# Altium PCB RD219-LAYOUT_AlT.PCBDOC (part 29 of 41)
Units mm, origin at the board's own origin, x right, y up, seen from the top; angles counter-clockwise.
Board outline 209.75 x 159.97 mm, 2 copper layers (TOP, BOTTOM), stack 0 mm thick; 398 components, 199 nets, 1469 pads, 0 vias.
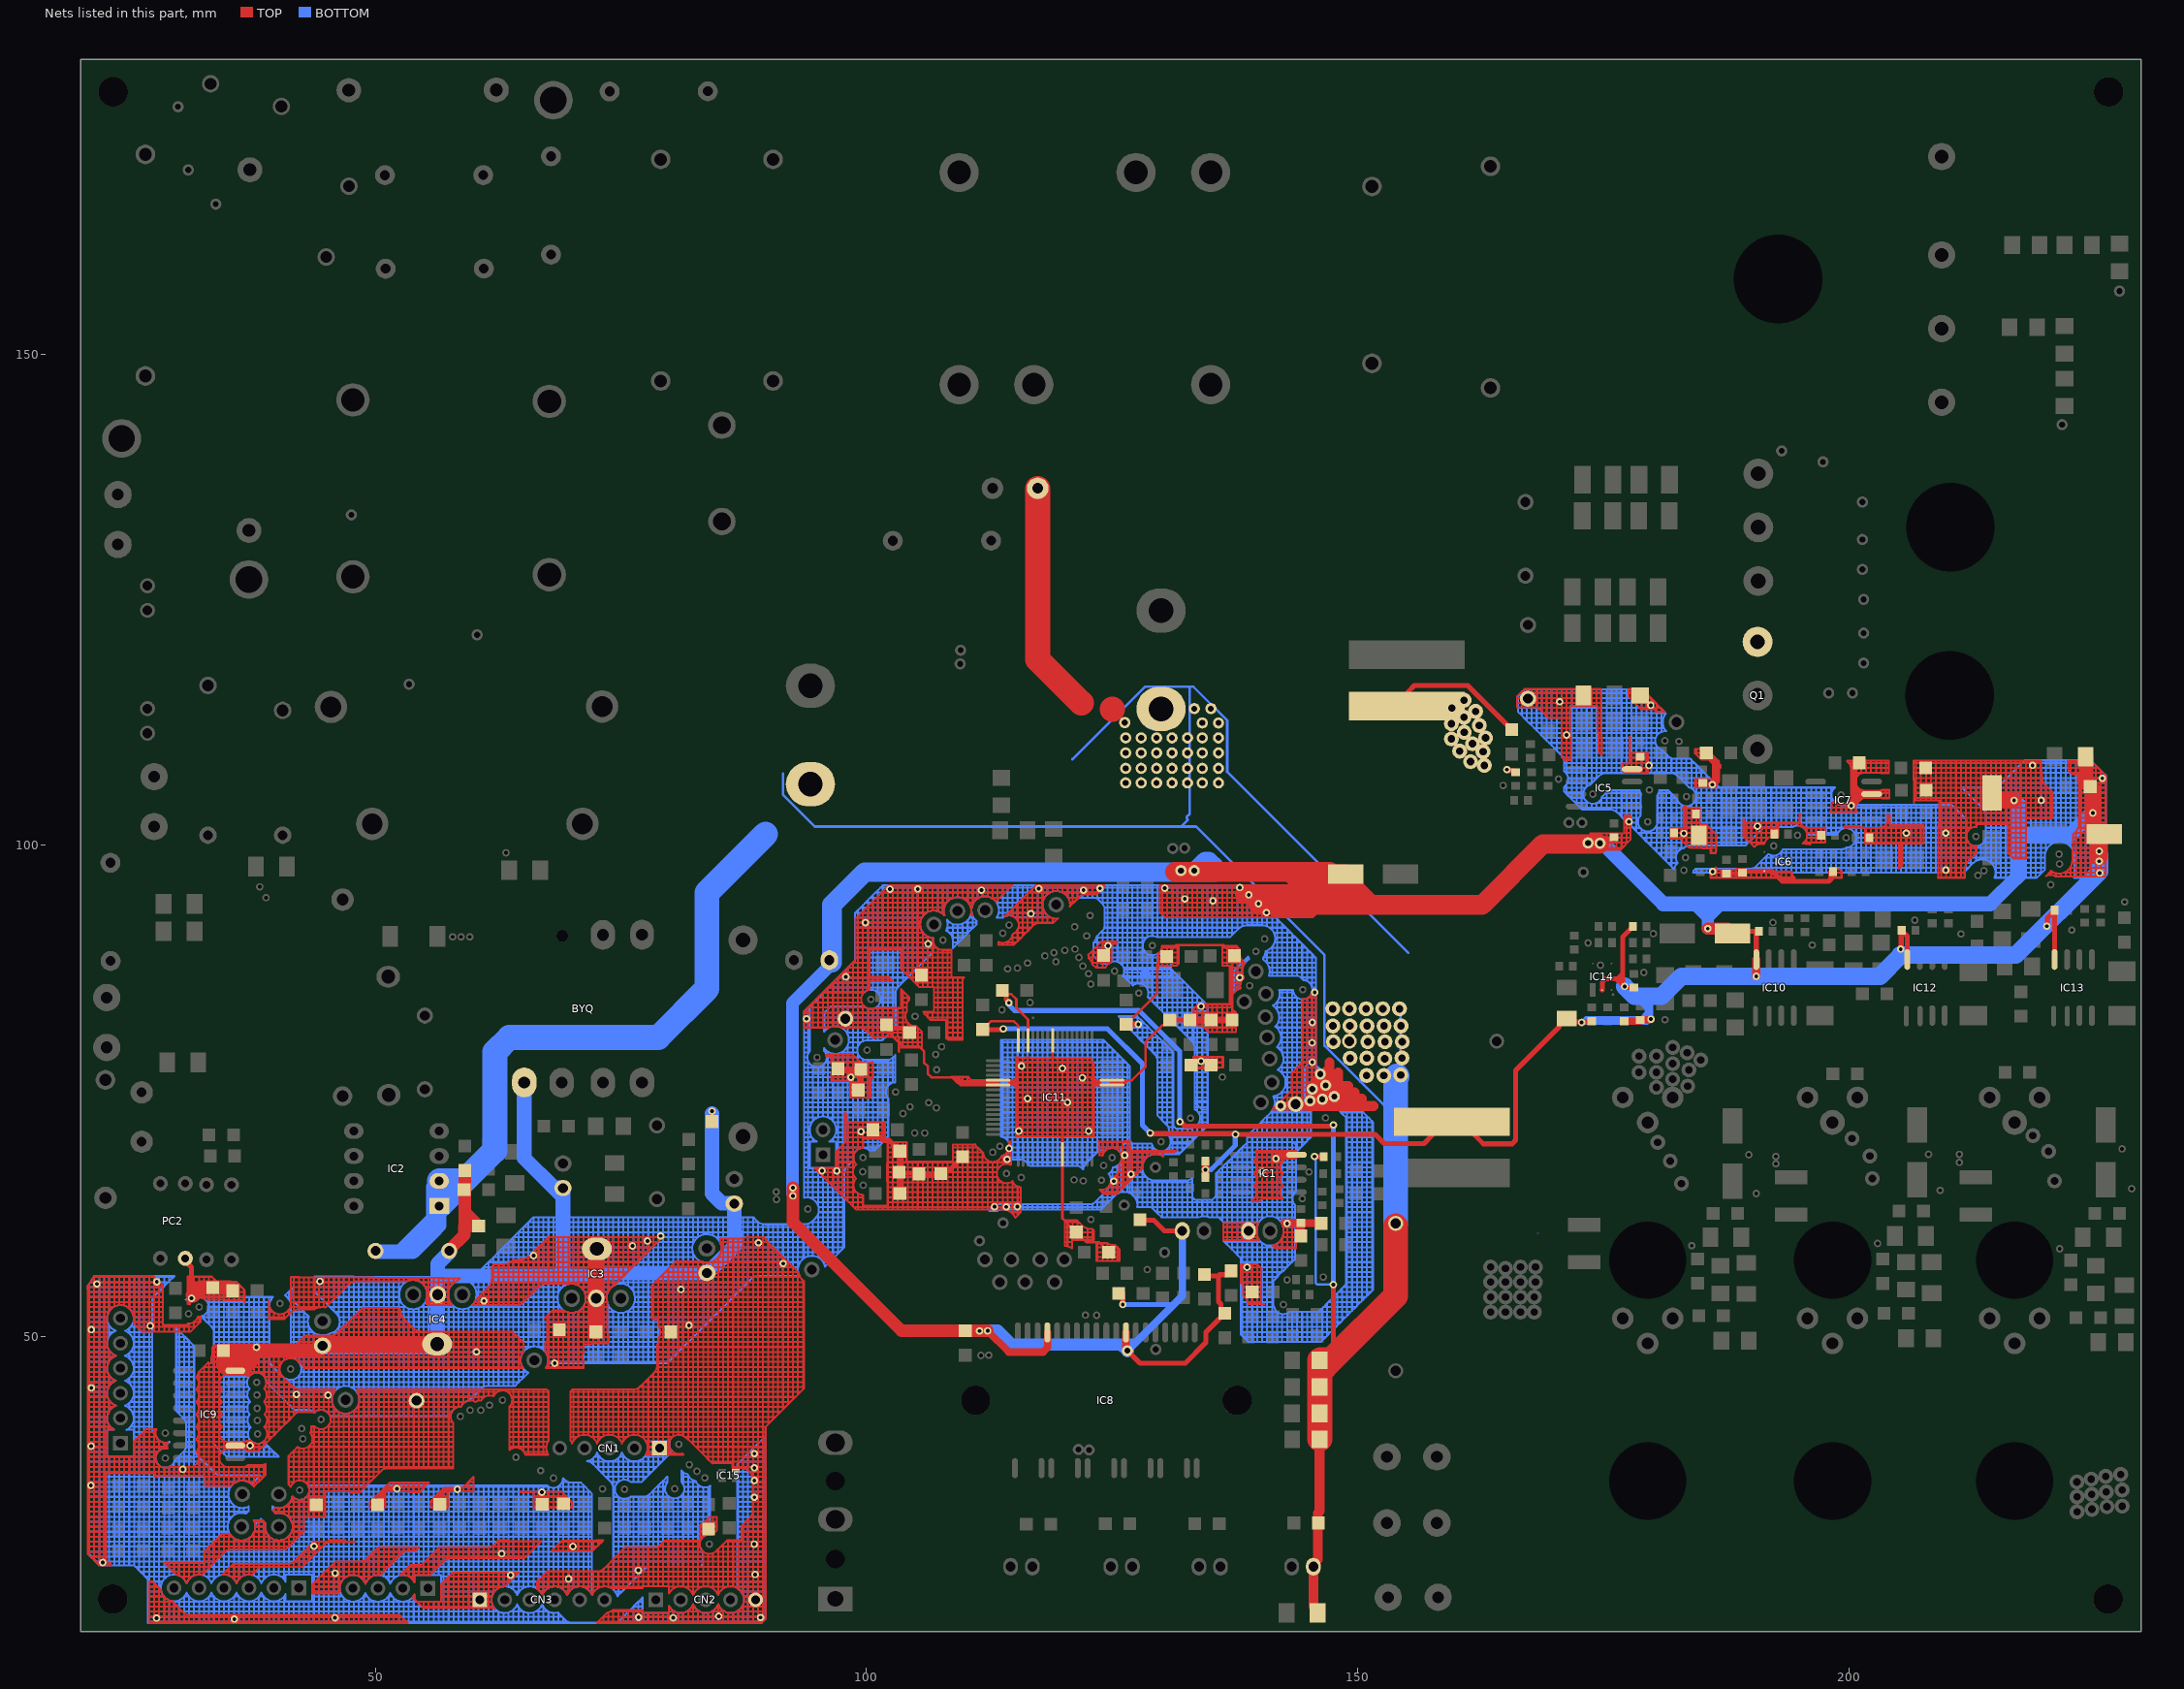
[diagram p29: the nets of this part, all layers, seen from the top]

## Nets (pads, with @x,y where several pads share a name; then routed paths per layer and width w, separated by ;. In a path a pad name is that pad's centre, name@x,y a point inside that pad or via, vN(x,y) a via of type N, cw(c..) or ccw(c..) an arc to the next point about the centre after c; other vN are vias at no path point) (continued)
GND: (continued)
  BOTTOM w0.203: 88.453,36.256 88.961,36.256 ; pad.@88.453,36.764 88.453,37.272 ; pad.@88.453,36.764 pad.@88.961,36.764 ; 88.453,37.272 pad.@88.453,37.78 ; 88.453,37.272 88.961,37.272 ; pad.@88.453,37.78 pad.@88.453,38.288 ; pad.@88.453,37.78 88.961,37.78 ; pad.@88.453,38.288 88.453,38.634 ; pad.@88.453,38.288 88.961,38.288 ; 88.453,38.634 88.615,38.796 ; 88.453,56.027 cw(c88.875,55.433) 88.518,56.068 ; 88.453,56.027 cw(c88.875,55.433) 88.518,56.068 ; 88.453,56.027 88.453,56.068 ; 88.453,56.068 88.453,56.576 ; 88.453,56.068 88.518,56.068 ; 88.453,56.576 88.453,57.084 ; 88.453,56.576 88.961,56.576 ; 88.453,57.084 88.453,57.592 ; 88.453,57.084 88.961,57.084 ; 88.453,57.592 88.453,58.1 ; 88.453,57.592 88.961,57.592 ; 88.453,58.1 88.453,58.608 ; 88.453,58.1 88.961,58.1 ; 88.453,58.608 88.453,59.116 ; 88.453,58.608 88.961,58.608 ; 88.453,59.116 88.961,59.116 ; 88.453,59.116 88.453,59.624 ; 88.453,59.624 88.453,60.132 ; 88.453,59.624 pad.@88.961,59.624 ; 88.453,60.132 88.453,60.64 ; 88.453,60.132 88.961,60.132 ; 88.453,60.64 88.961,60.64 ; 88.453,60.64 88.453,61.148 ; 88.453,61.148 88.453,61.656 ; 88.453,61.148 88.961,61.148 ; 88.453,61.656 88.961,61.656 ; 88.453,61.656 88.453,62.164 ; 88.453,62.164 88.464,62.164 88.831,61.798 ; 88.518,56.068 cw(c88.875,55.433) 88.875,56.162 ; 88.518,56.068 cw(c88.875,55.433) 88.875,56.162 ; 88.615,38.796 88.961,38.796 ; 88.615,38.796 88.961,39.142 ; 88.831,61.798 ccw(c89.705,62.672) 88.961,61.684 ; 88.831,61.798 ccw(c89.705,62.672) 88.961,61.684 ; 88.875,56.162 88.961,56.162 ; 88.961,20.889 88.961,21.016 ; 88.961,20.889 89.215,20.889 89.342,21.016 ; 88.961,21.016 pad.@88.961,21.524 ; 88.961,21.016 89.342,21.016 ; pad.@88.961,21.524 88.961,22.032 ; pad.@88.961,21.524 pad.@89.469,21.524 ; 88.961,22.032 CN2.5@88.961,22.54 ; 88.961,22.032 89.469,22.032 ; CN2.5@88.961,22.54 CN2.5@88.961,23.048 ; CN2.5@88.961,22.54 89.469,22.54 ; CN2.5@88.961,23.048 89.469,23.048 ; CN2.5@88.961,23.048 CN2.5@88.961,23.556 ; CN2.5@88.961,23.556 88.961,24.064 ; CN2.5@88.961,23.556 89.469,23.556 ; 88.961,24.064 88.961,24.572 ; 88.961,24.064 89.469,24.064 ; 88.961,24.572 89.469,24.572 ; 88.961,24.572 88.961,25.08 ; 88.961,25.08 pad.@88.961,25.588 ; 88.961,25.08 89.469,25.08 ; pad.@88.961,25.588 89.469,25.588 ; pad.@88.961,25.588 88.961,26.096 ; 88.961,26.096 88.961,26.604 ; 88.961,26.096 89.469,26.096 ; 88.961,26.604 88.961,27.112 ; 88.961,26.604 89.469,26.604 ; 88.961,27.112 88.961,27.62 ; 88.961,27.112 89.469,27.112 ; 88.961,27.62 88.961,28.128 ; 88.961,27.62 89.469,27.62 ; 88.961,28.128 88.961,28.636 ; 88.961,28.128 89.469,28.128 ; 88.961,28.636 89.469,28.636 ; 88.961,28.636 88.961,29.144 ; 88.961,29.144 88.961,29.652 ; 88.961,29.144 89.469,29.144 ; 88.961,29.652 88.961,30.16 ; 88.961,29.652 89.469,29.652 ; 88.961,30.16 88.961,30.668 ; 88.961,30.16 89.469,30.16 ; 88.961,30.668 88.961,31.176 ; 88.961,30.668 89.469,30.668 ; 88.961,31.176 88.961,31.684 ; 88.961,31.176 89.469,31.176 ; 88.961,31.684 88.961,32.192 ; 88.961,31.684 89.469,31.684 ; 88.961,32.192 88.961,32.7 ; 88.961,32.192 89.469,32.192 ; 88.961,32.7 88.961,33.208 ; 88.961,32.7 89.469,32.7 ; 88.961,33.208 89.469,33.208 ; 88.961,33.208 pad.@88.961,33.716 ; pad.@88.961,33.716 88.961,34.224 ; pad.@88.961,33.716 89.469,33.716 ; 88.961,34.224 88.961,34.732 ; 88.961,34.224 89.469,34.224 ; 88.961,34.732 88.961,35.24 ; 88.961,34.732 89.469,34.732 ; 88.961,35.24 89.469,35.24 ; 88.961,35.24 88.961,35.748 ; 88.961,35.748 88.961,36.256 ; 88.961,35.748 89.469,35.748 ; 88.961,36.256 89.469,36.256 ; 88.961,36.256 pad.@88.961,36.764 ; pad.@88.961,36.764 88.961,37.272 ; pad.@88.961,36.764 89.469,36.764 ; 88.961,37.272 88.961,37.78 ; 88.961,37.272 89.469,37.272 ; 88.961,37.78 89.469,37.78 ; 88.961,37.78 88.961,38.288 ; 88.961,38.288 88.961,38.796 ; 88.961,38.288 89.469,38.288 ; 88.961,38.796 88.961,39.142 ; 88.961,38.796 89.469,38.796 ; 88.961,39.142 89.123,39.304 ; 88.961,56.162 88.961,56.576 ; 88.961,56.162 89.469,56.162 ; 88.961,56.576 88.961,57.084 ; 88.961,56.576 89.469,56.576 ; 88.961,57.084 88.961,57.592 ; 88.961,57.084 89.469,57.084 ; 88.961,57.592 88.961,58.1 ; 88.961,57.592 89.469,57.592 ; 88.961,58.1 88.961,58.608 ; 88.961,58.1 89.469,58.1 ; 88.961,58.608 88.961,59.116 ; 88.961,58.608 89.469,58.608 ; 88.961,59.116 pad.@88.961,59.624 ; 88.961,59.116 89.469,59.116 ; pad.@88.961,59.624 88.961,60.132 ; pad.@88.961,59.624 89.469,59.624 ; 88.961,60.132 88.961,60.64 ; 88.961,60.132 89.469,60.132 ; 88.961,60.64 89.469,60.64 ; 88.961,60.64 88.961,61.148 ; 88.961,61.148 88.961,61.656 ; 88.961,61.148 89.469,61.148 ; 88.961,61.656 88.961,61.684 ; 88.961,61.656 89,61.656 ; 88.961,61.684 ccw(c89.705,62.672) 89,61.656 ; 88.961,61.684 ccw(c89.705,62.672) 89,61.656 ; 89,61.656 ccw(c89.705,62.672) 89.469,61.458 ; 89,61.656 ccw(c89.705,62.672) 89.469,61.458 ; 89.123,39.304 89.469,39.65 ; 89.123,39.304 89.469,39.304 ; 89.342,21.016 89.469,21.143 ; 89.469,21.143 pad.@89.469,21.524 ; 89.469,21.143 89.723,21.397 89.723,21.524 ; pad.@89.469,21.524 89.723,21.524 ; pad.@89.469,21.524 89.469,22.032 ; 89.469,22.032 89.469,22.54 ; 89.469,22.032 89.723,22.032 ; 89.469,22.54 89.469,23.048 ; 89.469,22.54 89.723,22.54 ; 89.469,23.048 89.723,23.048 ; 89.469,23.048 89.469,23.556 ; 89.469,23.556 89.469,24.064 ; 89.469,23.556 89.723,23.556 ; 89.469,24.064 89.469,24.572 ; 89.469,24.064 89.723,24.064 ; 89.469,24.572 89.469,25.08 ; 89.469,24.572 89.723,24.572 ; 89.469,25.08 89.469,25.588 ; 89.469,25.08 89.723,25.08 ; 89.469,25.588 89.469,26.096 ; 89.469,25.588 89.723,25.588 ; 89.469,26.096 89.469,26.604 ; 89.469,26.096 89.723,26.096 ; 89.469,26.604 89.469,27.112 ; 89.469,26.604 89.723,26.604 ; 89.469,27.112 89.469,27.62 ; 89.469,27.112 89.723,27.112 ; 89.469,27.62 89.469,28.128 ; 89.469,27.62 89.723,27.62 ; 89.469,28.128 89.469,28.636 ; 89.469,28.128 89.723,28.128 ; 89.469,28.636 89.469,29.144 ; 89.469,28.636 89.723,28.636 ; 89.469,29.144 89.469,29.652 ; 89.469,29.144 89.723,29.144 ; 89.469,29.652 89.469,30.16 ; 89.469,29.652 89.723,29.652 ; 89.469,30.16 89.469,30.668 ; 89.469,30.16 89.723,30.16 ; 89.469,30.668 89.469,31.176 ; 89.469,30.668 89.723,30.668 ; 89.469,31.176 89.469,31.684 ; 89.469,31.176 89.723,31.176 ; 89.469,31.684 89.469,32.192 ; 89.469,31.684 89.723,31.684 ; 89.469,32.192 89.469,32.7 ; 89.469,32.192 89.723,32.192 ; 89.469,32.7 89.469,33.208 ; 89.469,32.7 89.723,32.7 ; 89.469,33.208 89.469,33.716 ; 89.469,33.208 89.723,33.208 ; 89.469,33.716 89.469,34.224 ; 89.469,33.716 89.723,33.716 ; 89.469,34.224 89.469,34.732 ; 89.469,34.224 89.723,34.224 ; 89.469,34.732 89.469,35.24 ; 89.469,34.732 89.723,34.732 ; 89.469,35.24 89.469,35.748 ; 89.469,35.24 89.723,35.24 ; 89.469,35.748 89.469,36.256 ; 89.469,35.748 89.723,35.748 ; 89.469,36.256 89.469,36.764 ; 89.469,36.256 89.723,36.256 ; 89.469,36.764 89.469,37.272 ; 89.469,36.764 89.723,36.764 ; 89.469,37.272 89.469,37.78 ; 89.469,37.272 89.723,37.272 ; 89.469,37.78 89.469,38.288 ; 89.469,37.78 89.723,37.78 ; 89.469,38.288 89.469,38.796 ; 89.469,38.288 89.723,38.288 ; 89.469,38.796 89.469,39.304 ; 89.469,38.796 89.723,38.796 ; 89.469,39.304 89.469,39.65 ; 89.469,39.304 89.723,39.304 ; 89.469,39.65 89.631,39.812 ; 89.469,56.162 89.469,56.576 ; 89.469,56.162 89.977,56.162 ; 89.469,56.576 89.469,57.084 ; 89.469,56.576 89.977,56.576 ; 89.469,57.084 89.469,57.592 ; 89.469,57.084 89.977,57.084 ; 89.469,57.592 89.469,58.1 ; 89.469,57.592 89.977,57.592 ; 89.469,58.1 89.469,58.608 ; 89.469,58.1 89.977,58.1 ; 89.469,58.608 89.469,59.116 ; 89.469,58.608 89.977,58.608 ; 89.469,59.116 89.977,59.116 ; 89.469,59.116 89.469,59.624 ; 89.469,59.624 89.469,60.132 ; 89.469,59.624 89.977,59.624 ; 89.469,60.132 89.469,60.64 ; 89.469,60.132 89.977,60.132 ; 89.469,60.64 89.469,61.148 ; 89.469,60.64 89.977,60.64 ; 89.469,61.148 89.977,61.148 ; 89.469,61.148 89.469,61.458 ; 89.469,61.458 ccw(c89.705,62.672) 89.705,61.435 ; 89.469,61.458 ccw(c89.705,62.672) 89.705,61.435 ; 89.631,39.812 89.723,39.812 ; 89.631,39.812 89.723,39.904 89.723,39.812 ; 89.705,61.435 89.977,61.435 ; 89.723,21.524 89.723,22.032 ; 89.723,22.032 89.723,22.54 ; 89.723,22.54 89.723,23.048 ; 89.723,23.048 89.723,23.556 ; 89.723,23.556 89.723,24.064 ; 89.723,24.064 89.723,24.572 ; 89.723,24.572 89.723,25.08 ; 89.723,25.08 89.723,25.588 ; 89.723,25.588 89.723,26.096 ; 89.723,26.096 89.723,26.604 ; 89.723,26.604 89.723,27.112 ; 89.723,27.112 89.723,27.62 ; 89.723,27.62 89.723,28.128 ; 89.723,28.128 89.723,28.636 ; 89.723,28.636 89.723,29.144 ; 89.723,29.144 89.723,29.652 ; 89.723,29.652 89.723,30.16 ; 89.723,30.16 89.723,30.668 ; 89.723,30.668 89.723,31.176 ; 89.723,31.176 89.723,31.684 ; 89.723,31.684 89.723,32.192 ; 89.723,32.192 89.723,32.7 ; 89.723,32.7 89.723,33.208 ; 89.723,33.208 89.723,33.716 ; 89.723,33.716 89.723,34.224 ; 89.723,34.224 89.723,34.732 ; 89.723,34.732 89.723,35.24 ; 89.723,35.24 89.723,35.748 ; 89.723,35.748 89.723,36.256 ; 89.723,36.256 89.723,36.764 ; 89.723,36.764 89.723,37.272 ; 89.723,37.272 89.723,37.78 ; 89.723,37.78 89.723,38.288 ; 89.723,38.288 89.723,38.796 ; 89.723,38.796 89.723,39.304 ; 89.723,39.304 89.723,39.812 ; 89.977,56.162 89.977,56.576 ; 89.977,56.162 90.485,56.162 ; 89.977,56.576 89.977,57.084 ; 89.977,56.576 90.485,56.576 ; 89.977,57.084 89.977,57.592 ; 89.977,57.084 90.485,57.084 ; 89.977,57.592 89.977,58.1 ; 89.977,57.592 90.485,57.592 ; 89.977,58.1 89.977,58.608 ; 89.977,58.1 90.485,58.1 ; 89.977,58.608 89.977,59.116 ; 89.977,58.608 90.485,58.608 ; 89.977,59.116 89.977,59.624 ; 89.977,59.116 90.485,59.116 ; 89.977,59.624 89.977,60.132 ; 89.977,59.624 90.485,59.624 ; 89.977,60.132 89.977,60.64 ; 89.977,60.132 90.485,60.132 ; 89.977,60.64 89.977,61.148 ; 89.977,60.64 90.485,60.64 ; 89.977,61.148 89.977,61.435 ; 89.977,61.148 90.485,61.148 ; 89.977,61.435 90.485,61.435 ; 90.485,56.162 90.485,56.576 ; 90.485,56.162 90.993,56.162 ; 90.485,56.576 90.485,57.084 ; 90.485,56.576 90.993,56.576 ; 90.485,57.084 90.485,57.592 ; 90.485,57.084 90.993,57.084 ; 90.485,57.592 90.485,58.1 ; 90.485,57.592 90.993,57.592 ; 90.485,58.1 90.485,58.608 ; 90.485,58.1 90.993,58.1 ; 90.485,58.608 90.485,59.116 ; 90.485,58.608 90.993,58.608 ; 90.485,59.116 90.485,59.624 ; 90.485,59.116 90.993,59.116 ; 90.485,59.624 90.485,60.132 ; 90.485,59.624 90.993,59.624 ; 90.485,60.132 90.485,60.64 ; 90.485,60.132 90.993,60.132 ; 90.485,60.64 90.485,61.148 ; 90.485,60.64 90.993,60.64 ; 90.485,61.148 90.485,61.435 ; 90.485,61.148 90.993,61.148 ; 90.485,61.435 90.993,61.435 ; 90.993,56.162 90.993,56.576 ; 90.993,56.162 91.501,56.162 ; 90.993,56.576 90.993,57.084 ; 90.993,56.576 91.501,56.576 ; 90.993,57.084 90.993,57.592 ; 90.993,57.084 pad.@91.501,57.084 ; 90.993,57.592 90.993,58.1 ; 90.993,57.592 pad.@91.501,57.592 ; 90.993,58.1 90.993,58.608 ; 90.993,58.1 91.501,58.1 ; 90.993,58.608 90.993,59.116 ; 90.993,58.608 91.501,58.608 ; 90.993,59.116 90.993,59.624 ; 90.993,59.116 91.501,59.116 ; 90.993,59.624 90.993,60.132 ; 90.993,59.624 91.501,59.624 ; 90.993,60.132 90.993,60.64 ; 90.993,60.132 91.501,60.132 ; 90.993,60.64 90.993,61.148 ; 90.993,60.64 91.501,60.64 ; 90.993,61.148 90.993,61.435 ; 90.993,61.148 91.501,61.148 ; 90.993,61.435 91.501,61.435 ; 91.501,56.162 91.501,56.576 ; 91.501,56.162 92.009,56.162 ; 91.501,56.576 pad.@91.501,57.084 ; 91.501,56.576 92.009,56.576 ; pad.@91.501,57.084 pad.@91.501,57.592 ; pad.@91.501,57.084 92.009,57.084 ; pad.@91.501,57.592 91.501,58.1 ; pad.@91.501,57.592 92.009,57.592 ; 91.501,58.1 91.501,58.608 ; 91.501,58.1 92.009,58.1 ; 91.501,58.608 91.501,59.116 ; 91.501,58.608 92.009,58.608 ; 91.501,59.116 91.501,59.624 ; 91.501,59.116 92.009,59.116 ; 91.501,59.624 91.501,60.132 ; 91.501,59.624 92.009,59.624 ; 91.501,60.132 91.501,60.64 ; 91.501,60.132 92.009,60.132 ; 91.501,60.64 91.501,61.148 ; 91.501,60.64 92.009,60.64 ; 91.501,61.148 91.501,61.435 ; 91.501,61.148 92.009,61.148 ; 91.501,61.435 92.009,61.435 ; 92.009,56.162 92.009,56.576 ; 92.009,56.162 92.517,56.162 ; 92.009,56.576 92.009,57.084 ; 92.009,56.576 92.517,56.576 ; 92.009,57.084 92.009,57.592 ; 92.009,57.084 92.517,57.084 ; 92.009,57.592 92.009,58.1 ; 92.009,57.592 92.517,57.592 ; 92.009,58.1 92.009,58.608 ; 92.009,58.1 92.517,58.1 ; 92.009,58.608 92.009,59.116 ; 92.009,58.608 92.517,58.608 ; 92.009,59.116 92.009,59.624 ; 92.009,59.116 92.517,59.116 ; 92.009,59.624 92.009,60.132 ; 92.009,59.624 92.517,59.624 ; 92.009,60.132 92.009,60.64 ; 92.009,60.132 92.517,60.132 ; 92.009,60.64 92.009,61.148 ; 92.009,60.64 92.517,60.64 ; 92.009,61.148 92.009,61.435 ; 92.009,61.148 92.517,61.148 ; 92.009,61.435 92.517,61.435 ; 92.517,56.162 93.025,56.162 ; 92.517,56.162 92.517,56.576 ; 92.517,56.576 93.025,56.576 ; 92.517,56.576 92.517,57.084 ; 92.517,57.084 93.025,57.084 ; 92.517,57.084 92.517,57.592 ; 92.517,57.592 92.517,58.1 ; 92.517,57.592 93.025,57.592 ; 92.517,58.1 93.025,58.1 ; 92.517,58.1 92.517,58.608 ; 92.517,58.608 92.517,59.116 ; 92.517,58.608 93.025,58.608 ; 92.517,59.116 93.025,59.116 ; 92.517,59.116 92.517,59.624 ; 92.517,59.624 92.517,60.132 ; 92.517,59.624 93.025,59.624 ; 92.517,60.132 92.517,60.64 ; 92.517,60.132 93.025,60.132 ; 92.517,60.64 93.025,60.64 ; 92.517,60.64 92.517,61.148 ; 92.517,61.148 92.517,61.435 ; 92.517,61.148 93.025,61.148 ; 92.517,61.435 93.025,61.435 ; 93.025,56.162 93.025,56.576 ; 93.025,56.576 93.025,56.717 ; 93.025,56.576 93.044,56.576 ; 93.025,56.717 cw(c94.422,56.83) 93.025,56.943 ; 93.025,56.717 ccw(c94.422,56.83) 93.044,56.576 ; 93.025,56.943 cw(c94.422,56.83) 93.044,57.084 ; 93.025,56.943 93.025,57.084 ; 93.025,57.084 93.025,57.592 ; 93.025,57.084 93.044,57.084 ; 93.025,57.592 93.025,58.1 ; 93.025,57.592 93.246,57.592 ; 93.025,58.1 93.025,58.608 ; 93.025,58.1 93.533,58.1 ; 93.025,58.608 93.025,59.116 ; 93.025,58.608 93.533,58.608 ; 93.025,59.116 93.025,59.624 ; 93.025,59.116 93.533,59.116 ; 93.025,59.624 93.025,60.132 ; 93.025,59.624 93.533,59.624 ; 93.025,60.132 93.025,60.64 ; 93.025,60.132 93.533,60.132 ; 93.025,60.64 93.025,61.148 ; 93.025,60.64 93.533,60.64 ; 93.025,61.148 93.025,61.435 ; 93.025,61.148 93.533,61.148 ; 93.025,61.435 93.533,61.435 ; 93.044,57.084 cw(c94.422,56.83) 93.246,57.592 ; 93.246,57.592 cw(c94.422,56.83) 93.247,57.593 cw(c94.422,56.83) 93.533,57.914 ; 93.533,57.914 cw(c94.422,56.83) 93.659,58.005 cw(c94.422,56.83) 93.66,58.006 ; 93.533,57.914 93.533,58.1 ; 93.533,58.1 93.533,58.608 ; 93.533,58.1 93.66,58.1 ; 93.533,58.608 93.533,59.116 ; 93.533,58.608 93.66,58.608 ; 93.533,59.116 93.533,59.624 ; 93.533,59.116 93.66,59.116 ; 93.533,59.624 93.533,60.132 ; 93.533,59.624 93.66,59.624 ; 93.533,60.132 93.533,60.64 ; 93.533,60.132 93.66,60.132 ; 93.533,60.64 93.533,61.148 ; 93.533,60.64 93.66,60.64 ; 93.533,61.148 93.533,61.435 ; 93.533,61.148 93.66,61.148 ; 93.533,61.435 93.66,61.435 ; 93.66,58.006 cw(c94.422,56.83) 93.829,58.1 ; 93.66,58.006 93.66,58.1 ; 93.66,58.1 93.66,58.608 ; 93.66,58.1 93.829,58.1 ; 93.66,58.608 93.66,59.116 ; 93.66,58.608 94.041,58.608 ; 93.66,59.116 93.66,59.624 ; 93.66,59.116 94.041,59.116 ; 93.66,59.624 94.041,59.624 ; 93.66,59.624 93.66,60.132 ; 93.66,60.132 93.66,60.64 ; 93.66,60.132 94.041,60.132 ; 93.66,60.64 93.66,61.148 ; 93.66,60.64 94.041,60.64 ; 93.66,61.148 94.041,61.148 ; 93.66,61.148 93.66,61.435 ; 93.66,61.435 ccw(c93.66,62.672) 94.041,61.496 ; 93.66,61.435 ccw(c93.66,62.672) 94.041,61.496 ; 93.66,64.136 cw(c93.914,62.926) 94.041,64.156 ; 93.66,64.136 93.66,64.196 ; 93.66,64.196 93.66,64.704 ; 93.66,64.196 94.041,64.196 ; 93.66,64.704 94.041,64.704 ; 93.66,64.704 93.66,65.212 ; 93.66,65.212 94.041,65.212 ; 93.66,65.212 93.66,65.72 ; 93.66,65.72 94.041,65.72 ; 93.66,65.72 93.66,66.228 ; 93.66,66.228 93.66,66.736 ; 93.66,66.228 94.041,66.228 ; 93.66,66.736 93.66,67.244 ; 93.66,66.736 94.041,66.736 ; 93.66,67.244 93.66,67.752 ; 93.66,67.244 94.041,67.244 ; 93.66,67.752 94.041,67.752 ; 93.66,67.752 93.66,68.26 ; 93.66,68.26 94.041,68.26 ; 93.66,68.26 93.66,68.768 ; 93.66,68.768 94.041,68.768 ; 93.66,68.768 93.66,69.276 ; 93.66,69.276 93.66,69.784 ; 93.66,69.276 94.041,69.276 ; 93.66,69.784 93.66,70.292 ; 93.66,69.784 94.041,69.784 ; 93.66,70.292 94.041,70.292 ; 93.66,70.292 93.66,70.8 ; 93.66,70.8 94.041,70.8 ; 93.66,70.8 93.66,71.308 ; 93.66,71.308 94.041,71.308 ; 93.66,71.308 93.66,71.816 ; 93.66,71.816 94.041,71.816 ; 93.66,71.816 93.66,72.324 ; 93.66,72.324 94.041,72.324 ; 93.66,72.324 93.66,72.832 ; 93.66,72.832 94.041,72.832 ; 93.66,72.832 93.66,73.34 ; 93.66,73.34 94.041,73.34 ; 93.66,73.34 93.66,73.848 ; 93.66,73.848 93.66,74.356 ; 93.66,73.848 94.041,73.848 ; 93.66,74.356 93.66,74.864 ; 93.66,74.356 94.041,74.356 ; 93.66,74.864 93.66,75.372 ; 93.66,74.864 94.041,74.864 ; 93.66,75.372 93.66,75.88 ; 93.66,75.372 94.041,75.372 ; 93.66,75.88 93.66,76.388 ; 93.66,75.88 94.041,75.88 ; 93.66,76.388 94.041,76.388 ; 93.66,76.388 93.66,76.896 ; 93.66,76.896 94.041,76.896 ; 93.66,76.896 93.66,77.404 ; 93.66,77.404 94.041,77.404 ; 93.66,77.404 93.66,77.912 ; 93.66,77.912 94.041,77.912 ; 93.66,77.912 93.66,78.42 ; 93.66,78.42 93.66,78.928 ; 93.66,78.42 93.982,78.42 ; 93.66,78.928 94.041,78.928 ; 93.66,78.928 93.66,79.436 ; 93.66,79.436 94.041,79.436 ; 93.66,79.436 93.66,79.944 ; 93.66,79.944 94.041,79.944 ; 93.66,79.944 93.66,80.452 ; 93.66,80.452 94.041,80.452 ; 93.66,80.452 93.66,80.96 ; 93.66,80.96 94.041,80.96 ; 93.66,80.96 93.66,81.468 ; 93.66,81.468 94.041,81.468 ; 93.66,81.468 93.66,81.976 ; 93.66,81.976 pad.@93.66,82.484 ; 93.66,81.976 94.041,81.976 ; pad.@93.66,82.484 93.66,82.992 ; pad.@93.66,82.484 pad.@94.041,82.484 ; 93.66,82.992 93.66,83.119 94.041,83.5 ; 93.66,82.992 94.041,82.992 ; 93.829,58.1 cw(c94.422,56.83) 94.036,58.177 cw(c94.422,56.83) 94.041,58.179 ; 93.982,78.42 ccw(c94.965,78.418) 93.982,78.418 ccw(c94.965,78.418) 94.041,78.083 ; 93.982,78.42 cw(c94.965,78.418) 94.041,78.753 ; 94.041,58.179 cw(c94.422,56.83) 94.549,58.226 ; 94.041,58.179 94.041,58.608 ; 94.041,58.608 94.041,59.116 ; 94.041,58.608 94.549,58.608 ; 94.041,59.116 94.549,59.116 ; 94.041,59.116 94.041,59.624 ; 94.041,59.624 94.041,60.132 ; 94.041,59.624 94.549,59.624 ; 94.041,60.132 94.041,60.64 ; 94.041,60.132 94.549,60.132 ; 94.041,60.64 94.549,60.64 ; 94.041,60.64 94.041,61.148 ; 94.041,61.148 94.549,61.148 ; 94.041,61.148 94.041,61.496 ; 94.041,64.156 cw(c93.914,62.926) 94.043,64.156 cw(c93.914,62.926) 94.549,63.987 ; 94.041,64.156 94.041,64.196 ; 94.041,64.196 94.041,64.704 ; 94.041,64.196 94.549,64.196 ; 94.041,64.704 94.041,65.212 ; 94.041,64.704 94.549,64.704 ; 94.041,65.212 94.041,65.72 ; 94.041,65.212 94.549,65.212 ; 94.041,65.72 94.041,66.228 ; 94.041,65.72 94.549,65.72 ; 94.041,66.228 94.041,66.736 ; 94.041,66.228 94.549,66.228 ; 94.041,66.736 94.041,67.244 ; 94.041,66.736 94.549,66.736 ; 94.041,67.244 94.041,67.752 ; 94.041,67.244 94.213,67.244 ; 94.041,67.752 94.041,68.26 ; 94.041,67.752 94.213,67.752 ; 94.041,68.26 94.041,68.768 ; 94.041,68.26 94.213,68.26 ; 94.041,68.768 94.041,69.276 ; 94.041,68.768 94.213,68.768 ; 94.041,69.276 94.041,69.784 ; 94.041,69.276 94.213,69.276 ; 94.041,69.784 94.041,70.292 ; 94.041,69.784 94.213,69.784 ; 94.041,70.292 94.041,70.8 ; 94.041,70.292 94.449,70.292 ; 94.041,70.8 94.041,71.308 ; 94.041,70.8 94.238,70.8 ; 94.041,71.308 94.041,71.816 ; 94.041,71.308 94.238,71.308 ; 94.041,71.816 94.041,72.324 ; 94.041,71.816 94.449,71.816 ; 94.041,72.324 94.041,72.832 ; 94.041,72.324 94.549,72.324 ; 94.041,72.832 94.041,73.34 ; 94.041,72.832 94.549,72.832 ; 94.041,73.34 94.041,73.848 ; 94.041,73.34 94.549,73.34 ; 94.041,73.848 94.041,74.356 ; 94.041,73.848 94.549,73.848 ; 94.041,74.356 94.041,74.864 ; 94.041,74.356 94.549,74.356 ; 94.041,74.864 94.041,75.372 ; 94.041,74.864 94.549,74.864 ; 94.041,75.372 94.041,75.88 ; 94.041,75.372 94.549,75.372 ; 94.041,75.88 94.041,76.388 ; 94.041,75.88 94.549,75.88 ; 94.041,76.388 94.041,76.896 ; 94.041,76.388 94.549,76.388 ; 94.041,76.896 94.041,77.404 ; 94.041,76.896 94.549,76.896 ; 94.041,77.404 94.041,77.912 ; 94.041,77.404 94.549,77.404 ; 94.041,77.912 94.041,78.083 ; 94.041,77.912 94.123,77.912 ; 94.041,78.083 ccw(c94.965,78.418) 94.042,78.082 ccw(c94.965,78.418) 94.123,77.912 ; 94.041,78.753 cw(c94.965,78.418) 94.125,78.928 ; 94.041,78.753 94.041,78.928 ; 94.041,78.928 94.041,79.436 ; 94.041,78.928 94.125,78.928 ; 94.041,79.436 94.041,79.944 ; 94.041,79.436 94.236,79.436 ; 94.041,79.944 94.041,80.452 ; 94.041,79.944 94.236,79.944 ; 94.041,80.452 94.041,80.96 ; 94.041,80.452 94.236,80.452 ; 94.041,80.96 94.041,81.468 ; 94.041,80.96 94.236,80.96 ; 94.041,81.468 94.041,81.976 ; 94.041,81.468 94.236,81.468 ; 94.041,81.976 94.236,81.976 ; 94.041,81.976 pad.@94.041,82.484 ; pad.@94.041,82.484 94.041,82.992 ; pad.@94.041,82.484 pad.@94.236,82.484 ; 94.041,82.992 94.041,83.5 ; 94.041,82.992 94.236,82.992 ; 94.041,83.5 94.549,84.008 ; 94.041,83.5 94.27,83.5 ; 94.123,77.912 ccw(c94.965,78.418) 94.549,77.528 94.549,77.404 ; 94.213,67.244 94.213,67.752 ; 94.213,67.244 94.213,67.162 94.549,67.162 ; 94.213,67.752 94.213,68.26 ; 94.213,68.26 94.213,68.768 ; 94.213,68.768 94.213,69.276 ; 94.213,69.276 94.213,69.784 ; 94.213,69.784 94.213,69.866 94.549,69.866 ; 94.236,79.436 94.236,79.944 ; 94.236,79.944 94.236,80.452 ; 94.236,80.452 94.236,80.96 ; 94.236,80.96 94.236,81.468 ; 94.236,81.468 94.236,81.976 ; 94.236,81.976 pad.@94.236,82.484 ; pad.@94.236,82.484 94.236,82.992 ; 94.236,82.992 94.236,83.281 ; 94.236,83.281 cw(c94.965,83.281) 94.27,83.5 ; 94.236,83.281 cw(c94.965,83.281) 94.27,83.5 ; 94.238,70.8 ccw(c95.565,71.054) 94.238,70.796 ccw(c95.565,71.054) 94.444,70.298 ccw(c95.565,71.054) 94.449,70.292 ; 94.238,70.8 cw(c95.565,71.054) 94.213,71.054 cw(c95.565,71.054) 94.238,71.308 ; 94.238,71.308 cw(c95.565,71.054) 94.238,71.312 cw(c95.565,71.054) 94.444,71.81 cw(c95.565,71.054) 94.449,71.816 ; 94.27,83.5 cw(c94.965,83.281) 94.45,83.796 ; 94.27,83.5 cw(c94.965,83.281) 94.45,83.796 ; 94.365,61.656 cw(c93.66,62.672) 94.042,61.496 ccw(c93.66,62.672) 94.365,61.656 ; 94.365,61.656 ccw(c93.66,62.672) 94.369,61.659 ; 94.365,61.656 ccw(c93.66,62.672) 94.369,61.659 ; 94.365,61.656 94.549,61.656 ; 94.369,61.659 ccw(c93.66,62.672) 94.534,61.798 ; 94.369,61.659 ccw(c93.66,62.672) 94.534,61.798 ; 94.449,70.292 ccw(c95.565,71.054) 94.549,70.163 ; 94.449,71.816 cw(c95.565,71.054) 94.549,71.945 ; 94.45,83.796 94.549,83.895 ; 94.534,61.798 94.549,61.812 ; 94.549,58.226 cw(c94.422,56.83) 95.015,58.1 ; 94.549,58.226 94.549,58.608 ; 94.549,58.608 94.549,59.116 ; 94.549,58.608 95.057,58.608 ; 94.549,59.116 95.057,59.116 ; 94.549,59.116 94.549,59.624 ; 94.549,59.624 94.549,60.132 ; 94.549,59.624 95.057,59.624 ; 94.549,60.132 94.549,60.64 ; 94.549,60.132 95.057,60.132 ; 94.549,60.64 94.549,61.148 ; 94.549,60.64 95.057,60.64 ; 94.549,61.148 94.549,61.656 ; 94.549,61.148 95.057,61.148 ; 94.549,61.656 94.549,61.812 ; 94.549,61.656 95.057,61.656 ; 94.549,61.812 94.788,62.052 ccw(c93.914,62.926) 94.888,62.164 ; 94.549,63.987 cw(c93.914,62.926) 94.551,63.986 cw(c93.914,62.926) 94.888,63.688 ; 94.549,63.987 94.549,64.196 ; 94.549,64.196 94.549,64.704 ; 94.549,64.196 95.057,64.196 ; 94.549,64.704 94.549,65.212 ; 94.549,64.704 95.057,64.704 ; 94.549,65.212 94.549,65.72 ; 94.549,65.212 95.057,65.212 ; 94.549,65.72 94.549,66.228 ; 94.549,65.72 95.057,65.72 ; 94.549,66.228 94.549,66.736 ; 94.549,66.228 95.057,66.228 ; 94.549,66.736 94.549,67.162 ; 94.549,66.736 95.057,66.736 ; 94.549,67.162 95.057,67.162 ; 94.549,69.866 94.549,70.163 ; 94.549,71.945 cw(c95.565,71.054) 95.057,72.306 ; 94.549,71.945 94.549,72.324 ; 94.549,72.324 95.057,72.324 ; 94.549,72.324 94.549,72.832 ; 94.549,72.832 94.549,73.34 ; 94.549,72.832 95.057,72.832 ; 94.549,73.34 94.549,73.848 ; 94.549,73.34 95.057,73.34 ; 94.549,73.848 94.549,74.356 ; 94.549,73.848 95.057,73.848 ; 94.549,74.356 94.549,74.864 ; 94.549,74.356 95.057,74.356 ; 94.549,74.864 94.549,75.372 ; 94.549,74.864 95.057,74.864 ; 94.549,75.372 94.549,75.88 ; 94.549,75.372 95.057,75.372 ; 94.549,75.88 94.549,76.388 ; 94.549,75.88 95.057,75.88 ; 94.549,76.388 94.549,76.896 ; 94.549,76.388 95.057,76.388 ; 94.549,76.896 94.549,77.404 ; 94.549,76.896 95.057,76.896 ; 94.549,77.404 95.057,77.404 ; 94.549,83.895 94.662,84.008 ; 94.549,83.895 94.549,84.008 ; 94.549,84.008 95.057,84.516 ; 94.549,84.008 94.662,84.008 ; 94.662,84.008 95.057,84.403 ; 94.888,62.164 ccw(c93.914,62.926) 95.057,62.454 ; 94.888,62.164 95.057,62.164 ; 94.888,63.687 cw(c93.914,62.926) 95.057,63.398 ; 94.888,63.688 95.057,63.688 ; 95.015,58.1 cw(c94.422,56.83) 95.057,58.08 ; 95.015,58.1 95.057,58.1 ; 95.057,58.08 cw(c94.422,56.83) 95.058,58.079 cw(c94.422,56.83) 95.565,57.641 ; 95.057,58.08 95.057,58.1 ; 95.057,58.1 95.057,58.608 ; 95.057,58.1 95.565,58.1 ; 95.057,58.608 95.057,59.116 ; 95.057,58.608 95.565,58.608 ; 95.057,59.116 95.565,59.116 ; 95.057,59.116 95.057,59.624 ; 95.057,59.624 95.057,60.132 ; 95.057,59.624 95.565,59.624 ; 95.057,60.132 95.057,60.64 ; 95.057,60.132 95.565,60.132 ; 95.057,60.64 95.565,60.64 ; 95.057,60.64 95.057,61.148 ; 95.057,61.148 95.057,61.656 ; 95.057,61.148 95.565,61.148 ; 95.057,61.656 95.057,62.164 ; 95.057,61.656 95.565,61.656 ; 95.057,62.164 95.565,62.164 ; 95.057,62.164 95.057,62.454 ; 95.057,62.454 ccw(c93.914,62.926) 95.061,62.463 ccw(c93.914,62.926) 95.124,62.672 ; 95.057,63.398 cw(c93.914,62.926) 95.124,63.183 cw(c93.914,62.926) 95.124,63.18 ; 95.057,63.398 95.057,63.688 ; 95.057,63.688 95.057,64.196 ; 95.057,63.688 95.565,63.688 ; 95.057,64.196 95.565,64.196 ; 95.057,64.196 95.057,64.704 ; 95.057,64.704 95.057,65.212 ; 95.057,64.704 95.565,64.704 ; 95.057,65.212 95.057,65.72 ; 95.057,65.212 95.565,65.212 ; 95.057,65.72 95.057,66.228 ; 95.057,65.72 95.565,65.72 ; 95.057,66.228 95.057,66.736 ; 95.057,66.228 95.565,66.228 ; 95.057,66.736 pad.@95.565,66.736 ; 95.057,66.736 95.057,67.162 ; 95.057,67.162 pad.@95.565,67.162 ; 95.057,72.306 cw(c95.565,71.054) 95.103,72.324 ; 95.057,72.307 95.057,72.324 ; 95.057,72.324 95.057,72.832 ; 95.057,72.324 95.102,72.324 ; 95.057,72.832 95.057,73.34 ; 95.057,72.832 95.565,72.832 ; 95.057,73.34 95.057,73.848 ; 95.057,73.34 95.565,73.34 ; 95.057,73.848 95.057,74.356 ; 95.057,73.848 95.565,73.848 ; 95.057,74.356 95.057,74.864 ; 95.057,74.356 95.565,74.356 ; 95.057,74.864 95.057,75.372 ; 95.057,74.864 95.565,74.864 ; 95.057,75.372 95.057,75.88 ; 95.057,75.372 95.565,75.372 ; 95.057,75.88 95.057,76.388 ; 95.057,75.88 95.565,75.88 ; 95.057,76.388 95.057,76.896 ; 95.057,76.388 95.565,76.388 ; 95.057,76.896 95.057,77.404 ; 95.057,76.896 95.565,76.896 ; 95.057,77.404 95.565,77.404 ; 95.057,77.404 95.057,77.44 ; 95.057,77.44 ccw(c94.965,78.418) 95.565,77.64 ; 95.057,84.403 95.057,84.516 ; 95.057,84.403 95.17,84.516 ; 95.057,84.516 95.565,85.024 ; 95.057,84.516 95.17,84.516 ; 95.103,72.324 cw(c95.565,71.054) 95.565,72.406 ; 95.124,62.672 ccw(c93.914,62.926) 95.124,63.18 ; 95.124,62.672 95.565,62.672 ; 95.124,63.18 95.565,63.18 ; 95.17,84.516 95.503,84.849 ; 95.503,84.849 cw(c96.018,84.334) 95.565,84.905 ; 95.503,84.849 cw(c96.018,84.334) 95.565,84.905 ; 95.565,57.641 cw(c94.422,56.83) 95.598,57.592 ; 95.565,57.641 95.565,58.1 ; 95.565,58.1 95.565,58.608 ; 95.565,58.1 96.073,58.1 ; 95.565,58.608 95.565,59.116 ; 95.565,58.608 96.073,58.608 ; 95.565,59.116 95.565,59.624 ; 95.565,59.116 96.073,59.116 ; 95.565,59.624 95.565,60.132 ; 95.565,59.624 96.073,59.624 ; 95.565,60.132 95.565,60.64 ; 95.565,60.132 96.073,60.132 ; 95.565,60.64 95.565,61.148 ; 95.565,60.64 96.073,60.64 ; 95.565,61.148 95.565,61.656 ; 95.565,61.148 96.073,61.148 ; 95.565,61.656 95.565,62.164 ; 95.565,61.656 96.073,61.656 ; 95.565,62.164 95.565,62.672 ; 95.565,62.164 96.073,62.164 ; 95.565,62.672 95.565,63.18 ; 95.565,62.672 96.073,62.672 ; 95.565,63.18 95.565,63.688 ; 95.565,63.18 96.073,63.18 ; 95.565,63.688 95.565,64.196 ; 95.565,63.688 96.073,63.688 ; 95.565,64.196 96.073,64.196 ; 95.565,64.196 95.565,64.704 ; 95.565,64.704 95.565,65.212 ; 95.565,64.704 96.073,64.704 ; 95.565,65.212 95.565,65.72 ; 95.565,65.212 96.073,65.212 ; 95.565,65.72 95.565,66.228 ; 95.565,65.72 96.073,65.72 ; 95.565,66.228 pad.@95.565,66.736 ; 95.565,66.228 96.073,66.228 ; pad.@95.565,66.736 96.073,66.736 ; pad.@95.565,66.736 pad.@95.565,67.162 ; pad.@95.565,67.162 96.073,67.162 ; 95.565,72.406 cw(c95.565,71.054) 96.028,72.324 ; 95.565,72.406 95.565,72.832 ; 95.565,72.832 95.565,73.34 ; 95.565,72.832 96.073,72.832 ; 95.565,73.34 95.565,73.848 ; 95.565,73.34 96.073,73.34 ; 95.565,73.848 95.565,74.356 ; 95.565,73.848 96.073,73.848 ; 95.565,74.356 96.073,74.356 ; 95.565,74.356 95.565,74.864 ; 95.565,74.864 95.565,75.372 ; 95.565,74.864 96.073,74.864 ; 95.565,75.372 96.073,75.372 ; 95.565,75.372 95.565,75.88 ; 95.565,75.88 96.073,75.88 ; 95.565,75.88 95.565,76.388 ; 95.565,76.388 95.565,76.896 ; 95.565,76.388 96.073,76.388 ; 95.565,76.896 95.565,77.404 ; 95.565,76.896 96.073,76.896 ; 95.565,77.404 96.073,77.404 ; 95.565,77.404 95.565,77.64 ; 95.565,77.64 ccw(c94.965,78.418) 95.57,77.644 ccw(c94.965,78.418) 95.807,77.912 ; 95.565,84.905 cw(c96.018,84.334) 95.784,85.024 ; 95.565,84.905 cw(c96.018,84.334) 95.784,85.024 ; 95.565,84.905 95.565,85.024 ; 95.565,85.024 96.073,85.532 ; 95.565,85.024 95.784,85.024 ; 95.598,57.592 cw(c94.422,56.83) 95.788,57.146 96.073,57.431 ; 95.598,57.592 96.073,57.592 ; 95.693,79.342 ccw(c96.809,80.19) 96.073,78.998 ; 95.693,81.468 95.693,81.976 ; 95.693,81.468 96.073,81.468 ; 95.693,81.976 96.073,81.976 ; 95.693,81.976 95.693,82.484 ; 95.693,82.484 96.073,82.484 ; 95.693,82.484 95.693,82.979 95.706,82.992 ; 95.706,82.992 96.073,83.359 ; 95.706,82.992 96.073,82.992 ; 95.784,85.024 cw(c96.018,84.334) 96.018,85.062 ; 95.784,85.024 cw(c96.018,84.334) 96.018,85.062 ; 95.805,78.928 cw(c94.965,78.418) 95.947,78.42 ; 95.805,78.928 96.073,78.928 ; 95.807,77.912 ccw(c94.965,78.418) 95.947,78.418 ccw(c94.965,78.418) 95.947,78.42 ; 95.807,77.912 96.073,77.912 ; 95.947,78.42 96.073,78.42 ; 96.018,85.062 96.073,85.062 ; 96.028,72.324 cw(c95.565,71.054) 96.073,72.307 ; 96.028,72.324 96.073,72.324 ; 96.073,57.431 96.581,57.939 ; 96.073,57.431 96.073,57.592 ; 96.073,57.592 96.073,58.1 ; 96.073,58.1 96.073,58.608 ; 96.073,58.1 96.581,58.1 ; 96.073,58.608 96.073,59.116 ; 96.073,58.608 96.581,58.608 ; 96.073,59.116 96.073,59.624 ; 96.073,59.116 96.581,59.116 ; 96.073,59.624 96.073,60.132 ; 96.073,59.624 96.581,59.624 ; 96.073,60.132 96.073,60.64 ; 96.073,60.132 96.581,60.132 ; 96.073,60.64 96.073,61.148 ; 96.073,60.64 96.581,60.64 ; 96.073,61.148 96.073,61.656 ; 96.073,61.148 96.581,61.148 ; 96.073,61.656 96.073,62.164 ; 96.073,61.656 96.581,61.656 ; 96.073,62.164 96.073,62.672 ; 96.073,62.164 96.581,62.164 ; 96.073,62.672 96.073,63.18 ; 96.073,62.672 96.581,62.672 ; 96.073,63.18 96.073,63.688 ; 96.073,63.18 96.581,63.18 ; 96.073,63.688 96.073,64.196 ; 96.073,63.688 96.581,63.688 ; 96.073,64.196 96.073,64.704 ; 96.073,64.196 96.581,64.196 ; 96.073,64.704 96.073,65.212 ; 96.073,64.704 96.581,64.704 ; 96.073,65.212 96.073,65.72 ; 96.073,65.212 96.581,65.212 ; 96.073,65.72 96.073,66.228 ; 96.073,65.72 96.581,65.72 ; 96.073,66.228 96.073,66.736 ; 96.073,66.228 96.581,66.228 ; 96.073,66.736 96.073,67.162 ; 96.073,66.736 96.581,66.736 ; 96.073,67.162 96.581,67.162 ; 96.073,72.307 cw(c95.565,71.054) 96.581,71.945 ; 96.073,72.307 96.073,72.324 ; 96.073,72.324 96.581,72.324 ; 96.073,72.324 96.073,72.832 ; 96.073,72.832 96.073,73.34 ; 96.073,72.832 96.581,72.832 ; 96.073,73.34 96.073,73.848 ; 96.073,73.34 96.581,73.34 ; 96.073,73.848 96.073,74.356 ; 96.073,73.848 96.581,73.848 ; 96.073,74.356 96.581,74.356 ; 96.073,74.356 96.073,74.864 ; 96.073,74.864 96.073,75.372 ; 96.073,74.864 96.581,74.864 ; 96.073,75.372 96.073,75.88 ; 96.073,75.372 96.581,75.372 ; 96.073,75.88 96.581,75.88 ; 96.073,75.88 96.073,76.388 ; 96.073,76.388 96.073,76.896 ; 96.073,76.388 96.581,76.388 ; 96.073,76.896 96.073,77.404 ; 96.073,76.896 96.581,76.896 ; 96.073,77.404 96.073,77.912 ; 96.073,77.404 96.581,77.404 ; 96.073,77.912 96.073,78.42 ; 96.073,77.912 96.581,77.912 ; 96.073,78.42 96.581,78.42 ; 96.073,78.42 96.073,78.928 ; 96.073,78.928 96.2,78.928 ; 96.073,78.928 96.073,78.998 ; 96.073,78.998 ccw(c96.809,80.19) 96.2,78.928 ; 96.073,81.383 cw(c96.809,80.19) 96.233,81.468 ; 96.073,81.383 96.073,81.468 ; 96.073,81.468 96.073,81.976 ; 96.073,81.468 96.233,81.468 ; 96.073,81.976 96.073,82.484 ; 96.073,81.976 96.581,81.976 ; 96.073,82.484 96.073,82.992 ; 96.073,82.484 96.581,82.484 ; 96.073,82.992 96.073,83.359 ; 96.073,82.992 96.581,82.992 ; 96.073,83.359 96.214,83.5 ; 96.073,85.062 96.581,85.062 ; 96.073,85.062 96.073,85.532 ; 96.073,85.532 96.581,86.04 ; 96.073,85.532 96.581,85.532 ; 96.209,69.866 ccw(c95.565,71.054) 96.581,70.163 ; 96.209,69.866 96.581,69.866 ; 96.214,83.5 96.32,83.605 96.581,83.605 ; 96.214,83.5 96.581,83.5 ; 96.233,81.468 cw(c96.809,80.19) 96.581,81.573 ; 96.581,57.939 96.581,58.1 ; 96.581,57.939 96.742,58.1 ; 96.581,58.1 96.581,58.608 ; 96.581,58.1 96.742,58.1 ; 96.581,58.608 96.581,59.116 ; 96.581,58.608 97.089,58.608 ; 96.581,59.116 96.581,59.624 ; 96.581,59.116 97.089,59.116 ; 96.581,59.624 96.581,60.132 ; 96.581,59.624 97.089,59.624 ; 96.581,60.132 96.581,60.64 ; 96.581,60.132 97.089,60.132 ; 96.581,60.64 96.581,61.148 ; 96.581,60.64 97.089,60.64 ; 96.581,61.148 96.581,61.656 ; 96.581,61.148 97.089,61.148 ; 96.581,61.656 96.581,62.164 ; 96.581,61.656 97.089,61.656 ; 96.581,62.164 96.581,62.672 ; 96.581,62.164 97.089,62.164 ; 96.581,62.672 96.581,63.18 ; 96.581,62.672 97.089,62.672 ; 96.581,63.18 96.581,63.688 ; 96.581,63.18 97.089,63.18 ; 96.581,63.688 96.581,64.196 ; 96.581,63.688 97.089,63.688 ; 96.581,64.196 96.581,64.704 ; 96.581,64.196 97.089,64.196 ; 96.581,64.704 96.581,65.212 ; 96.581,64.704 97.089,64.704 ; 96.581,65.212 96.581,65.72 ; 96.581,65.212 97.089,65.212 ; 96.581,65.72 96.581,66.228 ; 96.581,65.72 97.089,65.72 ; 96.581,66.228 96.581,66.736 ; 96.581,66.228 97.089,66.228 ; 96.581,66.736 pad.@97.089,66.736 ; 96.581,66.736 96.581,67.162 ; 96.581,67.162 96.917,67.162 pad.@96.917,67.244 ; 96.581,69.866 96.917,69.866 96.917,69.784 ; 96.581,69.866 96.581,70.163 ; 96.581,70.163 ccw(c95.565,71.054) 96.681,70.292 ; 96.581,71.945 cw(c95.565,71.054) 96.585,71.941 cw(c95.565,71.054) 96.681,71.816 ; 96.581,71.945 96.581,72.324 ; 96.581,72.324 96.581,72.832 ; 96.581,72.324 97.089,72.324 ; 96.581,72.832 96.581,73.34 ; 96.581,72.832 97.089,72.832 ; 96.581,73.34 96.581,73.848 ; 96.581,73.34 97.089,73.34 ; 96.581,73.848 96.581,74.356 ; 96.581,73.848 97.089,73.848 ; 96.581,74.356 96.581,74.864 ; 96.581,74.356 97.089,74.356 ; 96.581,74.864 96.581,75.372 ; 96.581,74.864 97.089,74.864 ; 96.581,75.372 96.581,75.88 ; 96.581,75.372 97.089,75.372 ; 96.581,75.88 96.581,76.388 ; 96.581,75.88 97.089,75.88 ; 96.581,76.388 96.581,76.896 ; 96.581,76.388 97.089,76.388 ; 96.581,76.896 96.581,77.404 ; 96.581,76.896 97.089,76.896 ; 96.581,77.404 96.581,77.912 ; 96.581,77.404 97.089,77.404 ; 96.581,77.912 96.581,78.42 ; 96.581,77.912 97.089,77.912 ; 96.581,78.42 97.089,78.42 ; 96.581,81.573 cw(c96.809,80.19) 96.59,81.575 cw(c96.809,80.19) 97.089,81.564 ; 96.581,81.573 96.581,81.976 ; 96.581,81.976 96.581,82.484 ; 96.581,81.976 97.089,81.976 ; 96.581,82.484 96.581,82.992 ; 96.581,82.484 TP32.1@97.089,82.484 ; 96.581,82.992 96.581,83.5 ; 96.581,82.992 97.089,82.992 ; 96.581,83.5 96.581,83.605 ; 96.581,83.5 97.089,83.5 ; 96.581,83.605 97.089,83.605 ; 96.581,85.062 96.581,85.532 ; 96.581,85.062 97.089,85.062 ; 96.581,85.532 96.581,86.04 ; 96.581,85.532 97.089,85.532 ; 96.581,86.04 97.089,86.548 ; 96.581,86.04 97.089,86.04 ; 96.681,70.292 ccw(c95.565,71.054) 96.892,70.796 ccw(c95.565,71.054) 96.893,70.8 ; 96.681,70.292 97.089,70.292 ; 96.681,71.816 cw(c95.565,71.054) 96.892,71.312 cw(c95.565,71.054) 96.893,71.308 ; 96.681,71.816 97.089,71.816 ; 96.742,58.1 97.089,58.447 ; 96.893,70.8 ccw(c95.565,71.054) 96.917,71.054 ccw(c95.565,71.054) 96.893,71.308 ; 96.893,70.8 97.089,70.8 ; 96.893,71.308 97.089,71.308 ; pad.@96.917,67.244 96.917,67.752 ; pad.@96.917,67.244 97.089,67.244 ; 96.917,67.752 96.917,68.26 ; 96.917,67.752 97.089,67.752 ; 96.917,68.26 97.089,68.26 ; 96.917,68.26 96.917,68.768 ; 96.917,68.768 97.089,68.768 ; 96.917,68.768 96.917,69.276 ; 96.917,69.276 96.917,69.784 ; 96.917,69.276 97.089,69.276 ; 96.917,69.784 97.089,69.784 ; 97.089,58.447 97.089,58.608 ; 97.089,58.447 97.25,58.608 ; 97.089,58.608 97.089,59.116 ; 97.089,58.608 97.25,58.608 ; 97.089,59.116 97.089,59.624 ; 97.089,59.116 97.597,59.116 ; 97.089,59.624 97.089,60.132 ; 97.089,59.624 97.597,59.624 ; 97.089,60.132 97.089,60.64 ; 97.089,60.132 97.597,60.132 ; 97.089,60.64 97.089,61.148 ; 97.089,60.64 97.597,60.64 ; 97.089,61.148 97.089,61.656 ; 97.089,61.148 97.597,61.148 ; 97.089,61.656 97.089,62.164 ; 97.089,61.656 97.597,61.656 ; 97.089,62.164 97.089,62.672 ; 97.089,62.164 97.597,62.164 ; 97.089,62.672 97.089,63.18 ; 97.089,62.672 97.597,62.672 ; 97.089,63.18 97.089,63.688 ; 97.089,63.18 97.597,63.18 ; 97.089,63.688 97.089,64.196 ; 97.089,63.688 97.597,63.688 ; 97.089,64.196 97.089,64.704 ; 97.089,64.196 97.597,64.196 ; 97.089,64.704 97.089,65.212 ; 97.089,64.704 97.597,64.704 ; 97.089,65.212 97.089,65.72 ; 97.089,65.212 97.597,65.212 ; 97.089,65.72 97.089,66.228 ; 97.089,65.72 97.597,65.72 ; 97.089,66.228 pad.@97.089,66.736 ; 97.089,66.228 97.597,66.228 ; pad.@97.089,66.736 97.597,66.736 ; pad.@97.089,66.736 97.089,67.244 ; 97.089,67.244 97.089,67.752 ; 97.089,67.244 97.597,67.244 ; 97.089,67.752 97.089,68.26 ; 97.089,67.752 97.597,67.752 ; 97.089,68.26 97.089,68.768 ; 97.089,68.26 97.597,68.26 ; 97.089,68.768 97.089,69.276 ; 97.089,68.768 97.597,68.768 ; 97.089,69.276 97.089,69.784 ; 97.089,69.276 97.597,69.276 ; 97.089,69.784 97.597,69.784 ; 97.089,69.784 97.089,70.292 ; 97.089,70.292 97.089,70.8 ; 97.089,70.292 97.597,70.292 ; 97.089,70.8 97.089,71.308 ; 97.089,70.8 97.597,70.8 ; 97.089,71.308 97.089,71.816 ; 97.089,71.308 97.597,71.308 ; 97.089,71.816 97.089,72.324 ; 97.089,71.816 97.597,71.816 ; 97.089,72.324 97.089,72.832 ; 97.089,72.324 97.597,72.324 ; 97.089,72.832 97.089,73.34 ; 97.089,72.832 97.597,72.832 ; 97.089,73.34 97.089,73.848 ; 97.089,73.34 97.597,73.34 ; 97.089,73.848 97.089,74.356 ; 97.089,73.848 97.597,73.848 ; 97.089,74.356 97.089,74.864 ; 97.089,74.356 97.597,74.356 ; 97.089,74.864 97.089,75.372 ; 97.089,74.864 97.597,74.864 ; 97.089,75.372 97.089,75.88 ; 97.089,75.372 97.597,75.372 ; 97.089,75.88 97.089,76.388 ; 97.089,75.88 97.597,75.88 ; 97.089,76.388 97.089,76.896 ; 97.089,76.388 97.597,76.388 ; 97.089,76.896 97.089,77.404 ; 97.089,76.896 97.597,76.896 ; 97.089,77.404 97.089,77.912 ; 97.089,77.404 97.597,77.404 ; 97.089,77.912 97.089,78.42 ; 97.089,77.912 97.597,77.912 ; 97.089,78.42 97.597,78.42 ; 97.089,78.42 97.089,78.817 ; 97.089,78.817 ccw(c96.809,80.19) 97.101,78.819 ccw(c96.809,80.19) 97.418,78.928 ; 97.089,81.564 cw(c96.809,80.19) 97.385,81.468 ; 97.089,81.564 97.089,81.976 ; 97.089,81.976 TP32.1@97.597,81.976 ; 97.089,81.976 TP32.1@97.089,82.484 ; TP32.1@97.089,82.484 97.089,82.992 ; TP32.1@97.089,82.484 TP32.1@97.597,82.484 ; 97.089,82.992 97.089,83.5 ; 97.089,82.992 TP32.1@97.597,82.992 ; 97.089,83.5 97.089,83.605 ; 97.089,83.5 97.597,83.5 ; 97.089,83.605 97.597,83.605 ; 97.089,85.062 97.089,85.532 ; 97.089,85.062 97.597,85.062 ; 97.089,85.532 97.089,86.04 ; 97.089,85.532 97.597,85.532 ; 97.089,86.04 97.089,86.548 ; 97.089,86.04 97.597,86.04 ; 97.089,86.548 97.597,87.056 ; 97.089,86.548 pad.@97.597,86.548 ; 97.25,58.608 97.597,58.955 ; 97.385,81.468 97.597,81.468 ; 97.418,78.928 ccw(c96.809,80.19) 97.424,78.931 ccw(c96.809,80.19) 97.593,79.028 ccw(c96.809,80.19) 97.597,79.031 ; 97.418,78.928 97.597,78.928 ; 97.597,58.955 97.597,59.116 ; 97.597,58.955 97.757,59.116 ; 97.597,59.116 97.597,59.624 ; 97.597,59.116 97.757,59.116 ; 97.597,59.624 97.597,60.132 ; 97.597,59.624 97.757,59.624 ; 97.597,60.132 97.597,60.64 ; 97.597,60.132 97.757,60.132 ; 97.597,60.64 97.597,61.148 ; 97.597,60.64 97.757,60.64 ; 97.597,61.148 97.597,61.656 ; 97.597,61.148 97.757,61.148 ; 97.597,61.656 97.597,62.164 ; 97.597,61.656 97.757,61.656 ; 97.597,62.164 97.597,62.672 ; 97.597,62.164 97.757,62.164 ; 97.597,62.672 97.597,63.18 ; 97.597,62.672 97.757,62.672 ; 97.597,63.18 97.597,63.688 ; 97.597,63.18 97.757,63.18 ; 97.597,63.688 97.597,64.196 ; 97.597,63.688 97.757,63.688 ; 97.597,64.196 97.597,64.704 ; 97.597,64.196 97.757,64.196 ; 97.597,64.704 97.597,65.212 ; 97.597,64.704 97.757,64.704 ; 97.597,65.212 97.597,65.72 ; 97.597,65.212 97.757,65.212 ; 97.597,65.72 97.597,66.228 ; 97.597,65.72 97.757,65.72 ; 97.597,66.228 97.597,66.736 ; 97.597,66.228 97.757,66.228 ; 97.597,66.736 97.597,67.244 ; 97.597,66.736 97.757,66.736 ; 97.597,67.244 97.597,67.752 ; 97.597,67.244 97.964,67.244 ; 97.597,67.752 98.105,67.752 ; 97.597,67.752 97.597,68.26 ; 97.597,68.26 97.597,68.768 ; 97.597,68.26 98.105,68.26 ; 97.597,68.768 97.597,69.276 ; 97.597,68.768 98.105,68.768 ; 97.597,69.276 97.597,69.784 ; 97.597,69.276 98.105,69.276 ; 97.597,69.784 98.105,69.784 ; 97.597,69.784 97.597,70.292 ; 97.597,70.292 98.105,70.292 ; 97.597,70.292 97.597,70.8 ; 97.597,70.8 97.597,71.308 ; 97.597,70.8 98.105,70.8 ; 97.597,71.308 97.597,71.816 ; 97.597,71.308 98.105,71.308 ; 97.597,71.816 97.597,72.324 ; 97.597,71.816 98.105,71.816 ; 97.597,72.324 98.105,72.324 ; 97.597,72.324 97.597,72.832 ; 97.597,72.832 97.597,73.34 ; 97.597,72.832 98.105,72.832 ; 97.597,73.34 97.597,73.848 ; 97.597,73.34 98.105,73.34 ; 97.597,73.848 97.597,74.356 ; 97.597,73.848 98.105,73.848 ; 97.597,74.356 98.105,74.356 ; 97.597,74.356 97.597,74.864 ; 97.597,74.864 97.597,75.372 ; 97.597,74.864 98.105,74.864 ; 97.597,75.372 98.105,75.372 ; 97.597,75.372 97.597,75.88 ; 97.597,75.88 98.105,75.88 ; 97.597,75.88 97.597,76.388 ; 97.597,76.388 97.597,76.896 ; 97.597,76.388 pad.@98.105,76.388 ; 97.597,76.896 97.597,77.404 ; 97.597,76.896 98.105,76.896 ; 97.597,77.404 97.597,77.912 ; 97.597,77.404 98.105,77.404 ; 97.597,77.912 97.597,78.42 ; 97.597,77.912 98.105,77.912 ; 97.597,78.42 98.105,78.42 ; 97.597,78.42 97.597,78.928 ; 97.597,78.928 98.105,78.928 ; 97.597,78.928 97.597,79.031 ; 97.597,79.031 ccw(c96.809,80.19) 97.985,79.427 ccw(c96.809,80.19) 97.991,79.436 ; 97.597,81.468 TP32.1@97.597,81.976 ; 97.597,81.468 98.105,81.468 ; TP32.1@97.597,81.976 TP32.1@97.597,82.484 ; TP32.1@97.597,81.976 TP32.1@98.105,81.976 ; TP32.1@97.597,82.484 TP32.1@97.597,82.992 ; TP32.1@97.597,82.484 TP32.1@98.105,82.484 ; TP32.1@97.597,82.992 97.597,83.5 ; TP32.1@97.597,82.992 TP32.1@98.105,82.992 ; 97.597,83.5 97.597,83.605 ; 97.597,83.5 98.105,83.5 ; 97.597,83.605 98.105,83.605 ; 97.597,85.062 97.597,85.532 ; 97.597,85.062 98.105,85.062 ; 97.597,85.532 97.597,86.04 ; 97.597,85.532 98.105,85.532 ; 97.597,86.04 pad.@97.597,86.548 ; 97.597,86.04 98.105,86.04 ; pad.@97.597,86.548 pad.@98.105,86.548 ; pad.@97.597,86.548 97.597,87.056 ; 97.597,87.056 98.105,87.564 ; 97.597,87.056 98.105,87.056 ; 97.757,59.116 97.757,59.624 ; 97.757,59.624 97.757,60.132 ; 97.757,60.132 97.757,60.64 ; 97.757,60.64 97.757,61.148 ; 97.757,61.148 97.757,61.656 ; 97.757,61.656 97.757,62.164 ; 97.757,62.164 97.757,62.672 ; 97.757,62.672 97.757,63.18 ; 97.757,63.18 97.757,63.688 ; 97.757,63.688 97.757,64.196 ; 97.757,64.196 97.757,64.704 ; 97.757,64.704 97.757,65.212 ; 97.757,65.212 97.757,65.72 ; 97.757,65.72 97.757,66.228 ; 97.757,66.228 97.757,66.736 ; 97.757,66.736 cw(c98.486,66.736) 97.964,67.244 ; 97.757,66.736 cw(c98.486,66.736) 97.964,67.244 ; 97.964,67.244 cw(c98.486,66.736) 97.971,67.251 ; 97.964,67.244 cw(c98.486,66.736) 97.971,67.251 ; 97.971,67.251 98.105,67.385 ; 97.981,80.96 cw(c96.809,80.19) 97.985,80.954 cw(c96.809,80.19) 98.105,80.725 ; 97.981,80.96 98.105,80.96 ; 97.991,79.436 ccw(c96.809,80.19) 98.105,79.656 ; 97.991,79.436 98.105,79.436 ; 98.105,67.385 98.105,67.752 ; 98.105,67.385 98.472,67.752 ; 98.105,67.752 98.105,68.26 ; 98.105,67.752 98.472,67.752 ; 98.105,68.26 98.105,68.768 ; 98.105,68.26 98.613,68.26 ; 98.105,68.768 98.105,69.276 ; 98.105,68.768 98.613,68.768 ; 98.105,69.276 98.105,69.784 ; 98.105,69.276 98.613,69.276 ; 98.105,69.784 98.105,70.292 ; 98.105,69.784 98.613,69.784 ; 98.105,70.292 98.105,70.8 ; 98.105,70.292 98.613,70.292 ; 98.105,70.8 98.105,71.308 ; 98.105,70.8 98.613,70.8 ; 98.105,71.308 98.105,71.816 ; 98.105,71.308 98.613,71.308 ; 98.105,71.816 98.105,72.324 ; 98.105,71.816 98.613,71.816 ; 98.105,72.324 98.105,72.832 ; 98.105,72.324 98.613,72.324 ; 98.105,72.832 98.105,73.34 ; 98.105,72.832 98.613,72.832 ; 98.105,73.34 98.105,73.848 ; 98.105,73.34 98.613,73.34 ; 98.105,73.848 98.105,74.356 ; 98.105,73.848 98.613,73.848 ; 98.105,74.356 98.105,74.864 ; 98.105,74.356 98.613,74.356 ; 98.105,74.864 98.105,75.372 ; 98.105,74.864 98.613,74.864 ; 98.105,75.372 98.105,75.88 ; 98.105,75.372 98.613,75.372 ; 98.105,75.88 pad.@98.105,76.388 ; 98.105,75.88 98.613,75.88 ; pad.@98.105,76.388 98.105,76.896 ; pad.@98.105,76.388 pad.@98.613,76.388 ; 98.105,76.896 98.105,77.404 ; 98.105,76.896 98.613,76.896 ; 98.105,77.404 98.105,77.912 ; 98.105,77.404 98.613,77.404 ; 98.105,77.912 98.105,78.42 ; 98.105,77.912 98.613,77.912 ; 98.105,78.42 98.105,78.928 ; 98.105,78.42 98.613,78.42 ; 98.105,78.928 98.105,79.436 ; 98.105,78.928 98.613,78.928 ; 98.105,79.436 98.613,79.436 ; 98.105,79.436 98.105,79.656 ; 98.105,80.725 cw(c96.809,80.19) 98.185,80.458 cw(c96.809,80.19) 98.186,80.452 ; 98.105,80.725 98.105,80.96 ; 98.105,80.96 98.105,81.468 ; 98.105,80.96 98.613,80.96 ; 98.105,81.468 98.613,81.468 ; 98.105,81.468 TP32.1@98.105,81.976 ; TP32.1@98.105,81.976 98.613,81.976 ; TP32.1@98.105,81.976 TP32.1@98.105,82.484 ; TP32.1@98.105,82.484 TP32.1@98.105,82.992 ; TP32.1@98.105,82.484 TP32.1@98.613,82.484 ; TP32.1@98.105,82.992 98.613,82.992 ; TP32.1@98.105,82.992 98.105,83.5 ; 98.105,83.5 98.613,83.5 ; 98.105,83.5 98.105,83.605 ; 98.105,83.605 98.613,83.605 ; 98.105,85.062 98.105,85.532 ; 98.105,85.062 98.613,85.062 ; 98.105,85.532 98.105,86.04 ; 98.105,85.532 98.613,85.532 ; 98.105,86.04 pad.@98.105,86.548 ; 98.105,86.04 98.613,86.04 ; pad.@98.105,86.548 98.613,86.548 ; pad.@98.105,86.548 98.105,87.056 ; 98.105,87.056 98.105,87.564 ; 98.105,87.056 98.613,87.056 ; 98.105,87.564 98.613,88.072 ; 98.105,87.564 98.613,87.564 ; 98.186,80.452 98.613,80.452 ; 98.472,67.752 98.613,67.893 ; 98.613,67.893 98.613,68.26 ; 98.613,67.893 98.695,67.975 ; 98.613,68.26 98.613,68.768 ; 98.613,68.768 98.613,69.276 ; 98.613,68.768 98.816,68.768 ; 98.613,69.276 98.613,69.784 ; 98.613,69.276 99.121,69.276 ; 98.613,69.784 98.613,70.292 ; 98.613,69.784 99.121,69.784 ; 98.613,70.292 98.613,70.8 ; 98.613,70.292 99.121,70.292 ; 98.613,70.8 98.613,71.308 ; 98.613,70.8 pad.@99.121,70.8 ; 98.613,71.308 98.613,71.816 ; 98.613,71.308 99.121,71.308 ; 98.613,71.816 98.613,72.324 ; 98.613,71.816 99.121,71.816 ; 98.613,72.324 98.613,72.832 ; 98.613,72.324 99.121,72.324 ; 98.613,72.832 98.613,73.34 ; 98.613,72.832 99.121,72.832 ; 98.613,73.34 98.613,73.848 ; 98.613,73.34 99.121,73.34 ; 98.613,73.848 98.613,74.356 ; 98.613,73.848 99.121,73.848 ; 98.613,74.356 98.613,74.864 ; 98.613,74.356 99.121,74.356 ; 98.613,74.864 98.613,75.372 ; 98.613,74.864 99.121,74.864 ; 98.613,75.372 98.613,75.88 ; 98.613,75.372 99.121,75.372 ; 98.613,75.88 pad.@98.613,76.388 ; 98.613,75.88 99.121,75.88 ; pad.@98.613,76.388 99.121,76.388 ; pad.@98.613,76.388 98.613,76.896 ; 98.613,76.896 98.613,77.404 ; 98.613,76.896 99.121,76.896 ; 98.613,77.404 98.613,77.912 ; 98.613,77.404 99.121,77.404 ; 98.613,77.912 98.613,78.42 ; 98.613,77.912 99.121,77.912 ; 98.613,78.42 98.613,78.928 ; 98.613,78.42 99.121,78.42 ; 98.613,78.928 98.613,79.436 ; 98.613,78.928 99.078,78.928 ; 98.613,79.436 98.613,79.944 ; 98.613,79.436 99.086,79.436 ; 98.613,79.944 98.613,80.452 ; 98.613,79.944 99.121,79.944 ; 98.613,80.452 98.613,80.96 ; 98.613,80.452 99.121,80.452 ; 98.613,80.96 98.613,81.468 ; 98.613,80.96 99.121,80.96 ; 98.613,81.468 99.121,81.468 ; 98.613,81.468 98.613,81.976 ; 98.613,81.976 99.121,81.976 ; 98.613,81.976 TP32.1@98.613,82.484 ; TP32.1@98.613,82.484 98.613,82.992 ; TP32.1@98.613,82.484 99.121,82.484 ; 98.613,82.992 98.613,83.5 ; 98.613,82.992 99.121,82.992 ; 98.613,83.5 99.121,83.5 ; 98.613,83.5 98.613,83.605 ; 98.613,83.605 99.121,83.605 ; 98.613,85.062 98.613,85.532 ; 98.613,85.062 99.121,85.062 ; 98.613,85.532 98.613,86.04 ; 98.613,85.532 99.121,85.532 ; 98.613,86.04 98.613,86.548 ; 98.613,86.04 99.121,86.04 ; 98.613,86.548 98.613,87.056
